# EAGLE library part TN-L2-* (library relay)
SLIM POLARIZED RELAY NAiS 2 coil latched Source: http://www.mew-europe.com/.. en_ds_61019_0000.pdf
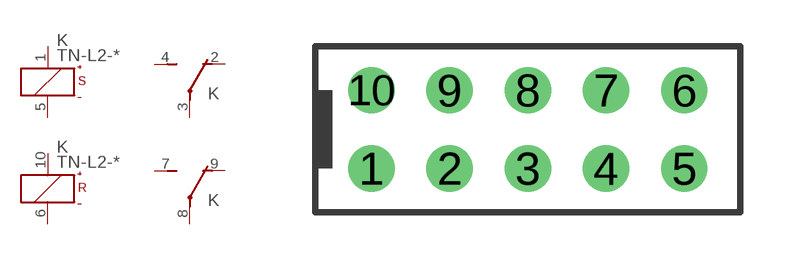
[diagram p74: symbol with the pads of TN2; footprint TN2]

Designator prefix K; gates S=K+-S R=K+-R 1=U 2=U

## TN-L2-3V (OC_FARNELL: unknown; OC_NEWARK: unknown), TN-L2-4.5V (OC_FARNELL: unknown; OC_NEWARK: unknown), TN-L2-5V (OC_FARNELL: unknown; OC_NEWARK: unknown), TN-L2-6V (OC_FARNELL: unknown; OC_NEWARK: unknown), TN-L2-9V (OC_FARNELL: unknown; OC_NEWARK: unknown), TN-L2-12V (OC_FARNELL: unknown; OC_NEWARK: unknown), TN-L2-24V (OC_FARNELL: unknown; OC_NEWARK: unknown)  [TN2]
1  S:+  pas
2  1:O  pas
3  1:P  pas
4  1:S  pas
5  S:-  pas
6  R:-  pas
7  2:S  pas
8  2:P  pas
9  2:O  pas
10  R:+  pas

## Footprint TN2 (pad centres in mm)
SLIM POLARIZED RELAY NAiS Source: http://www.mew-europe.com/.. en_ds_61019_0000.pdf
drill 1 round: 1 -5.08,-1.27; 2 -2.54,-1.27; 3 0,-1.27; 4 2.54,-1.27; 5 5.08,-1.27; 6 5.08,1.27; 7 2.54,1.27; 8 0,1.27; 9 -2.54,1.27; 10 -5.08,1.27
